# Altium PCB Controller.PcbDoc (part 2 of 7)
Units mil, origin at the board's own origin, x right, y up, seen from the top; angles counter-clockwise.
Board outline 9000 x 8000 mil, 6 copper layers (Top Layer, Layer 1, Layer 2, Layer 3, Layer 4, Bottom Layer), stack 61.699 mil thick; 761 components, 454 nets, 2369 pads, 1133 vias.
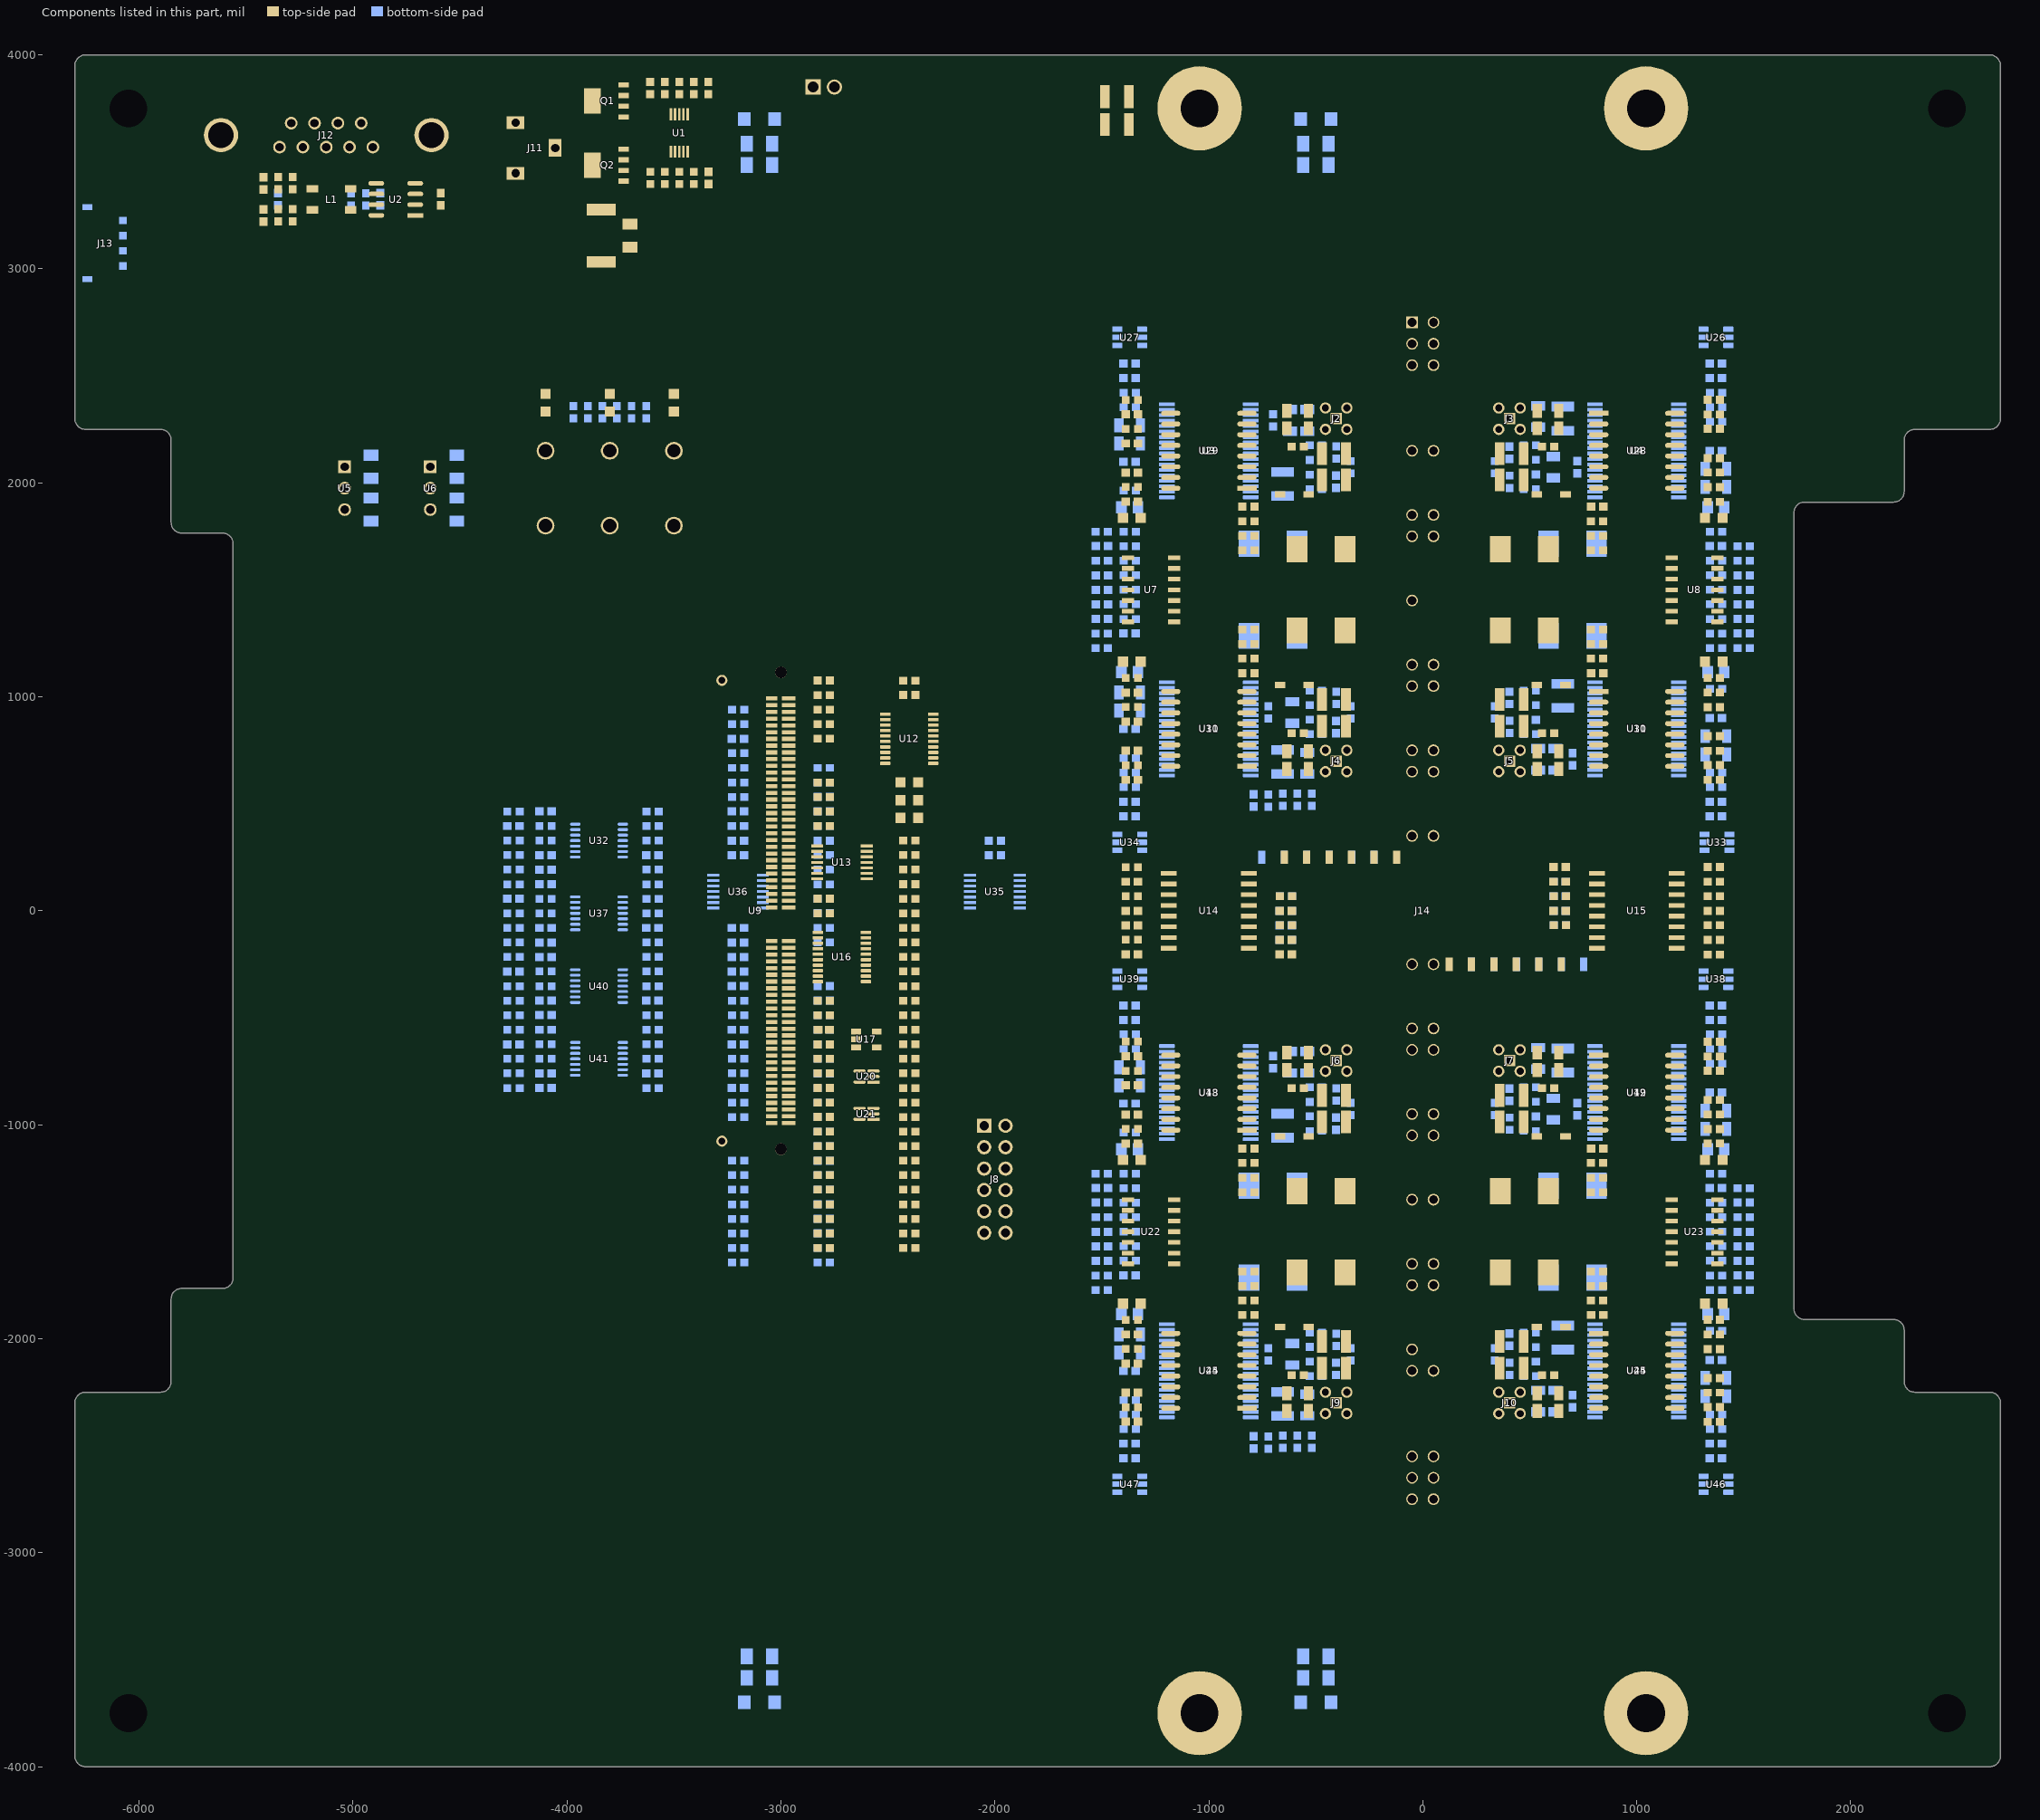
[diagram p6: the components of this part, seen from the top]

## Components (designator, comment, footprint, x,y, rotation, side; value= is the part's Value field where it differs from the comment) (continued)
R219 "RT0603BRD0716K2L" FP-MCR03-IPC_B -500,893 r180 bottom value=16.2kΩ
R220 "RT0603FRE0749K9L" FP-MCR03-IPC_B 405,859 r270 bottom value=49.9kΩ
R222 "CRCW060320K0FKTA" FP-MCR03-IPC_B -3200,872 r0 bottom value=20kΩ
R223 "RT0603DRE0730KL" FP-MCR03-IPC_B 500,825 r0 bottom value=30kΩ
R224 "RT0603BRD07107KL" FP-MCR03-IPC_B -500,825 r0 bottom value=107kΩ
R226 "RC1210JR-07330RL" RESC3125X70X40NL20T20 -655,695 r270 bottom value=330Ω
R227 "CRCW060320K0FKTA" FP-MCR03-IPC_B -3200,736 r0 bottom value=20kΩ
R228 "CRCW06030000Z0EB" FP-MCR03-IPC_B -1370,714 r180 bottom value=0Ω
R229 "RC0603FR-13330RL" FP-MCR03-IPC_B -2800,668 r180 bottom value=330Ω
R230 "CRCW060320K0FKTA" FP-MCR03-IPC_B -3200,668 r180 bottom value=20kΩ
R231 "ERJ3EKF1002V" FP-MCR03-IPC_B 1370,646 r0 bottom value=10kΩ
R232 "ERJ3EKF1002V" FP-MCR03-IPC_B -1370,646 r0 bottom value=10kΩ
R233 "RC0603FR-13330RL" FP-MCR03-IPC_B -2800,600 r180 bottom value=330Ω
R234 "CRCW060320K0FKTA" FP-MCR03-IPC_B -3200,600 r180 bottom value=20kΩ
R235 "RC0603JR-07120RL" FP-MCR03-IPC_B 1370,578 r0 bottom value=120Ω
R236 "RC0603JR-07120RL" FP-MCR03-IPC_B -1370,578 r0 bottom value=120Ω
R237 "CRCW06030000Z0EB" FP-MCR03-IPC_B -518,518 r270 bottom value=0Ω
R238 "RC0603FR-075K1L" FP-MCR03-IPC_B -586,518 r90 bottom value=5.1kΩ
R239 "ERJ-PB3B1801V" FP-MCR03-IPC_B -654,518 r270 bottom value=1.8kΩ
R240 "ERJ-PB3B1801V" FP-MCR03-IPC_B -722,515 r270 bottom value=1.8kΩ
R241 "CRCW060320K0FKTA" FP-MCR03-IPC_B -3200,532 r0 bottom value=20kΩ
R242 "CRCW060320K0FKTA" FP-MCR03-IPC_B -3600,464 r0 bottom value=20kΩ
R243 "CRCW060320K0FKTA" FP-MCR03-IPC_B -4250,464 r0 bottom value=20kΩ
R244 "RC0603FR-0727KL" FP-MCR03-IPC_B -3600,396 r0 bottom value=27kΩ
R245 "RC0603JR-101KL" FP-MCR03-IPC_B -4100,396 r0 bottom value=1kΩ
R246 "RC0603FR-0727KL" FP-MCR03-IPC_B -3600,328 r180 bottom value=27kΩ
R247 "RC0603JR-101KL" FP-MCR03-IPC_B -4100,328 r0 bottom value=1kΩ
R248 "RT0603BRD072K7L" FP-MCR03-IPC_B -4250,328 r0 bottom value=2.7kΩ
R249 "RC0603JR-07120RL" FP-MCR03-IPC_B -2800,260 r0 bottom value=120Ω
R250 "RC0603JR-07120RL" FP-MCR03-IPC_B -4250,260 r0 bottom value=120Ω
R251 "RNCF1206BKE1M00" RESC3116X65X40LL10T20 -280,250 r0 bottom value=1MΩ
R252 "RNCF1206BKE1M00" RESC3116X65X40LL10T20 -490,250 r0 bottom value=1MΩ
R253 "RNCF1206BKE1M00" RESC3116X65X40LL10T20 -700,250 r0 bottom value=1MΩ
R254 "RC0603JR-07120RL" FP-MCR03-IPC_B -2800,192 r0 bottom value=120Ω
R255 "ERJ3EKF1002V" FP-MCR03-IPC_B -3600,192 r180 bottom value=10kΩ
R256 "RT0603BRD072K7L" FP-MCR03-IPC_B -4250,192 r0 bottom value=2.7kΩ
R257 "RC0603JR-07120RL" FP-MCR03-IPC_B -2800,124 r0 bottom value=120Ω
R258 "CRCW060320K0FKTA" FP-MCR03-IPC_B -3600,124 r0 bottom value=20kΩ
R259 "CRCW060320K0FKTA" FP-MCR03-IPC_B -4250,124 r0 bottom value=20kΩ
R260 "ERA-3AEB5621V" FP-MCR03-IPC_B -640,68 r180 bottom value=5.62kΩ
R261 "RC0603JR-07120RL" FP-MCR03-IPC_B -2800,56 r0 bottom value=120Ω
R262 "RC0603FR-0727KL" FP-MCR03-IPC_B -3600,56 r0 bottom value=27kΩ
R263 "RC0603JR-101KL" FP-MCR03-IPC_B -4100,56 r0 bottom value=1kΩ
R264 "RC0603FR-0727KL" FP-MCR03-IPC_B -3600,-12 r180 bottom value=27kΩ
R265 "RC0603JR-101KL" FP-MCR03-IPC_B -4100,-12 r0 bottom value=1kΩ
R266 "RT0603BRD072K7L" FP-MCR03-IPC_B -4250,-12 r0 bottom value=2.7kΩ
R267 "ERA-3AEB5621V" FP-MCR03-IPC_B 640,-68 r0 bottom value=5.62kΩ
R268 "RC0603JR-07120RL" FP-MCR03-IPC_B -4250,-80 r0 bottom value=120Ω
R269 "ERJ3EKF1002V" FP-MCR03-IPC_B -2800,-148 r0 bottom value=10kΩ
R270 "ERJ3EKF1002V" FP-MCR03-IPC_B -3600,-148 r180 bottom value=10kΩ
R271 "RT0603BRD072K7L" FP-MCR03-IPC_B -4250,-148 r0 bottom value=2.7kΩ
R272 "CRCW060320K0FKTA" FP-MCR03-IPC_B -3600,-216 r0 bottom value=20kΩ
R273 "CRCW060320K0FKTA" FP-MCR03-IPC_B -4250,-216 r0 bottom value=20kΩ
R274 "RNCF1206BKE1M00" RESC3116X65X40LL10T20 700,-250 r180 bottom value=1MΩ
R275 "RNCF1206BKE1M00" RESC3116X65X40LL10T20 490,-250 r180 bottom value=1MΩ
R276 "RNCF1206BKE1M00" RESC3116X65X40LL10T20 280,-250 r180 bottom value=1MΩ
R277 "RC0603FR-0727KL" FP-MCR03-IPC_B -3600,-284 r0 bottom value=27kΩ
R278 "RC0603JR-101KL" FP-MCR03-IPC_B -4100,-284 r0 bottom value=1kΩ
R279 "RC0603FR-0727KL" FP-MCR03-IPC_B -3600,-352 r180 bottom value=27kΩ
R280 "RC0603JR-101KL" FP-MCR03-IPC_B -4100,-352 r0 bottom value=1kΩ
R281 "RT0603BRD072K7L" FP-MCR03-IPC_B -4250,-352 r0 bottom value=2.7kΩ
R282 "ERJ-3EKF49R9V" FP-MCR03-IPC_B -3200,-420 r0 bottom value=49.9Ω
R283 "RC0603JR-07120RL" FP-MCR03-IPC_B -4250,-420 r0 bottom value=120Ω
R284 "RC0603FR-075K49L" FP-MCR03-IPC_B -2800,-488 r0 bottom value=5.49kΩ
R285 "ERJ-3EKF49R9V" FP-MCR03-IPC_B -3200,-488 r0 bottom value=49.9Ω
R286 "ERJ3EKF1002V" FP-MCR03-IPC_B -3600,-488 r180 bottom value=10kΩ
R287 "RT0603BRD072K7L" FP-MCR03-IPC_B -4250,-488 r0 bottom value=2.7kΩ
R288 "RC0603FR-13330RL" FP-MCR03-IPC_B -2800,-556 r0 bottom value=330Ω
R289 "CRCW060320K0FKTA" FP-MCR03-IPC_B -3600,-556 r0 bottom value=20kΩ
R290 "CRCW060320K0FKTA" FP-MCR03-IPC_B -4250,-556 r0 bottom value=20kΩ
R291 "RC0603JR-07120RL" FP-MCR03-IPC_B 1370,-578 r180 bottom value=120Ω
R292 "RC0603JR-07120RL" FP-MCR03-IPC_B -1370,-578 r180 bottom value=120Ω
R293 "RC0603FR-0727KL" FP-MCR03-IPC_B -3600,-624 r0 bottom value=27kΩ
R294 "RC0603JR-101KL" FP-MCR03-IPC_B -4100,-624 r0 bottom value=1kΩ
R295 "ERJ3EKF1002V" FP-MCR03-IPC_B 1370,-646 r180 bottom value=10kΩ
R296 "RC1210JR-07330RL" RESC3125X70X40NL20T20 655,-700 r90 bottom value=330Ω
R297 "ERJ3EKF1002V" FP-MCR03-IPC_B -1370,-646 r180 bottom value=10kΩ
R298 "RT0603DRD0716K5L" FP-MCR03-IPC_B -2800,-692 r180 bottom value=16.5kΩ
R299 "ERJ-3EKF49R9V" FP-MCR03-IPC_B -3200,-692 r0 bottom value=49.9Ω
R300 "RC0603FR-0727KL" FP-MCR03-IPC_B -3600,-692 r180 bottom value=27kΩ
R301 "RC0603JR-101KL" FP-MCR03-IPC_B -4100,-692 r0 bottom value=1kΩ
R302 "RT0603BRD072K7L" FP-MCR03-IPC_B -4250,-692 r0 bottom value=2.7kΩ
R303 "CRCW06030000Z0EB" FP-MCR03-IPC_B 1370,-714 r0 bottom value=0Ω
R304 "ERJ-3EKF49R9V" FP-MCR03-IPC_B -3200,-760 r0 bottom value=49.9Ω
R305 "RC0603JR-07120RL" FP-MCR03-IPC_B -4250,-760 r0 bottom value=120Ω
R306 "RT0603BRD07107KL" FP-MCR03-IPC_B 500,-825 r180 bottom value=107kΩ
R307 "RT0603DRE0730KL" FP-MCR03-IPC_B -500,-825 r180 bottom value=30kΩ
R308 "RT0603DRD0716K5L" FP-MCR03-IPC_B -2800,-828 r0 bottom value=16.5kΩ
R309 "ERJ3EKF1002V" FP-MCR03-IPC_B -3600,-828 r180 bottom value=10kΩ
R310 "RT0603BRD072K7L" FP-MCR03-IPC_B -4250,-828 r0 bottom value=2.7kΩ
R311 "RT0603FRE0749K9L" FP-MCR03-IPC_B -405,-859 r90 bottom value=49.9kΩ
R312 "RT0603BRD0716K2L" FP-MCR03-IPC_B 500,-893 r0 bottom value=16.2kΩ
R313 "ERJ3EKF1002V" FP-MCR03-IPC_B -2800,-896 r0 bottom value=10kΩ
R314 "ERJ3EKF1002V" FP-MCR03-IPC_B -3200,-896 r180 bottom value=10kΩ
R315 "ERJ3EKF1002V" FP-MCR03-IPC_B 337,-927 r270 bottom value=10kΩ
R316 "ERJ3EKF1002V" FP-MCR03-IPC_B -337,-927 r270 bottom value=10kΩ
R317 "RC1210JR-07330RL" RESC3125X70X40NL20T20 -655,-1005 r270 bottom value=330Ω
R318 "RT0603BRD0716K2L" FP-MCR03-IPC_B -500,-961 r180 bottom value=16.2kΩ
R319 "ERJ3EKF1002V" FP-MCR03-IPC_B -3200,-964 r180 bottom value=10kΩ
R320 "RT0603FRE0749K9L" FP-MCR03-IPC_B 405,-995 r270 bottom value=49.9kΩ
R321 "RT0603DRE0730KL" FP-MCR03-IPC_B 500,-1029 r0 bottom value=30kΩ
R322 "RT0603BRD07107KL" FP-MCR03-IPC_B -500,-1029 r0 bottom value=107kΩ
R323 "CRCW06030000Z0EB" FP-MCR03-IPC_B -1370,-1037 r180 bottom value=0Ω
R324 "RC0805FR-07499RL" FP-MCR10-IPC_A 1370,-1115 r0 bottom value=499Ω
R325 "RC0805FR-07499RL" FP-MCR10-IPC_A -1370,-1115 r180 bottom value=499Ω
R326 "ERJ3EKF1002V" FP-MCR03-IPC_B -3200,-1168 r0 bottom value=10kΩ
R327 "ERJ3EKF1002V" FP-MCR03-IPC_B 1370,-1228 r180 bottom value=10kΩ
R328 "ERJ3EKF1002V" FP-MCR03-IPC_B -1370,-1228 r0 bottom value=10kΩ
R329 "ERJ3EKF1002V" FP-MCR03-IPC_B -1500,-1228 r180 bottom value=10kΩ
R330 "ERJ3EKF1002V" FP-MCR03-IPC_B -2800,-1236 r0 bottom value=10kΩ
R331 "ERJ3EKF1002V" FP-MCR03-IPC_B -3200,-1236 r0 bottom value=10kΩ
R332 "RC0603JR-07120RL" FP-MCR03-IPC_B 1500,-1296 r0 bottom value=120Ω
R333 "RC0603JR-07120RL" FP-MCR03-IPC_B -1370,-1296 r0 bottom value=120Ω
R334 "ERJ3EKF1002V" FP-MCR03-IPC_B -2800,-1304 r180 bottom value=10kΩ
R335 "ERJ3EKF1002V" FP-MCR03-IPC_B -3200,-1304 r180 bottom value=10kΩ
R336 "ERJ3EKF1002V" FP-MCR03-IPC_B 1370,-1364 r0 bottom value=10kΩ
R337 "RC0603JR-07120RL" FP-MCR03-IPC_B -1370,-1364 r0 bottom value=120Ω
R338 "ERJ3EKF1002V" FP-MCR03-IPC_B -3200,-1372 r180 bottom value=10kΩ
R339 "RC0603JR-07120RL" FP-MCR03-IPC_B 1370,-1432 r180 bottom value=120Ω
R340 "RC0603JR-07120RL" FP-MCR03-IPC_B -1370,-1432 r0 bottom value=120Ω
R341 "ERJ3EKF1002V" FP-MCR03-IPC_B -3200,-1440 r0 bottom value=10kΩ
R342 "RC0603JR-07120RL" FP-MCR03-IPC_B 1370,-1500 r180 bottom value=120Ω
R343 "RC0603JR-07120RL" FP-MCR03-IPC_B -1370,-1500 r0 bottom value=120Ω
R344 "ERJ3EKF1002V" FP-MCR03-IPC_B -3200,-1508 r0 bottom value=10kΩ
R345 "RC0603JR-07120RL" FP-MCR03-IPC_B 1370,-1568 r180 bottom value=120Ω
R346 "RC0603JR-07120RL" FP-MCR03-IPC_B -1370,-1568 r0 bottom value=120Ω
R347 "ERJ3EKF1002V" FP-MCR03-IPC_B -2800,-1576 r0 bottom value=10kΩ
R348 "ERJ3EKF1002V" FP-MCR03-IPC_B -3200,-1576 r180 bottom value=10kΩ
R349 "RC0603JR-07120RL" FP-MCR03-IPC_B 1370,-1636 r180 bottom value=120Ω
R350 "ERJ3EKF1002V" FP-MCR03-IPC_B -1370,-1636 r180 bottom value=10kΩ
R351 "ERJ3EKF1002V" FP-MCR03-IPC_B -2800,-1644 r0 bottom value=10kΩ
R352 "ERJ3EKF1002V" FP-MCR03-IPC_B -3200,-1644 r180 bottom value=10kΩ
R353 "RC0603JR-07120RL" FP-MCR03-IPC_B 1370,-1704 r180 bottom value=120Ω
R354 "RC0603JR-07120RL" FP-MCR03-IPC_B -1500,-1704 r180 bottom value=120Ω
R355 "ERJ3EKF1002V" FP-MCR03-IPC_B 1500,-1772 r0 bottom value=10kΩ
R356 "ERJ3EKF1002V" FP-MCR03-IPC_B 1370,-1772 r180 bottom value=10kΩ
R357 "ERJ3EKF1002V" FP-MCR03-IPC_B -1500,-1772 r0 bottom value=10kΩ
R358 "RC0805FR-07499RL" FP-MCR10-IPC_A 1370,-1885 r0 bottom value=499Ω
R359 "RC0805FR-07499RL" FP-MCR10-IPC_A -1370,-1885 r180 bottom value=499Ω
R360 "RC1210JR-07330RL" RESC3125X70X40NL20T20 655,-1995 r90 bottom value=330Ω
R361 "CRCW06030000Z0EB" FP-MCR03-IPC_B 1370,-1963 r0 bottom value=0Ω
R362 "RT0603BRD07107KL" FP-MCR03-IPC_B 500,-1971 r180 bottom value=107kΩ
R363 "RT0603DRE0730KL" FP-MCR03-IPC_B -500,-1971 r180 bottom value=30kΩ
R364 "RT0603FRE0749K9L" FP-MCR03-IPC_B -405,-2005 r90 bottom value=49.9kΩ
R365 "RT0603BRD0716K2L" FP-MCR03-IPC_B 500,-2039 r0 bottom value=16.2kΩ
R366 "ERJ3EKF1002V" FP-MCR03-IPC_B 337,-2073 r90 bottom value=10kΩ
R367 "ERJ3EKF1002V" FP-MCR03-IPC_B -337,-2073 r90 bottom value=10kΩ
R368 "RT0603BRD0716K2L" FP-MCR03-IPC_B -500,-2107 r180 bottom value=16.2kΩ
R369 "RT0603FRE0749K9L" FP-MCR03-IPC_B 405,-2141 r270 bottom value=49.9kΩ
R370 "RT0603DRE0730KL" FP-MCR03-IPC_B 500,-2175 r0 bottom value=30kΩ
R371 "RT0603BRD07107KL" FP-MCR03-IPC_B -500,-2175 r0 bottom value=107kΩ
R372 "RC1210JR-07330RL" RESC3125X70X40NL20T20 -655,-2305 r270 bottom value=330Ω
R373 "CRCW06030000Z0EB" FP-MCR03-IPC_B -1370,-2286 r180 bottom value=0Ω
R374 "ERJ3EKF1002V" FP-MCR03-IPC_B 1370,-2354 r180 bottom value=10kΩ
R375 "ERJ3EKF1002V" FP-MCR03-IPC_B -1370,-2354 r0 bottom value=10kΩ
R376 "RC0603JR-07120RL" FP-MCR03-IPC_B 1370,-2422 r0 bottom value=120Ω
R377 "RC0603JR-07120RL" FP-MCR03-IPC_B -1370,-2422 r0 bottom value=120Ω
R378 "CRCW06030000Z0EB" FP-MCR03-IPC_B -518,-2482 r270 bottom value=0Ω
R379 "RC0603FR-075K1L" FP-MCR03-IPC_B -586,-2482 r90 bottom value=5.1kΩ
R380 "ERJ-PB3B1801V" FP-MCR03-IPC_B -654,-2482 r270 bottom value=1.8kΩ
R381 "ERJ-PB3B1801V" FP-MCR03-IPC_B -722,-2485 r270 bottom value=1.8kΩ
R382 "RC1206FR-07249RL" FP-MCR18-IPC_A -500,-3485 r180 bottom value=249Ω
R383 "RC1206FR-07249RL" FP-MCR18-IPC_A -3100,-3485 r0 bottom value=249Ω
R384 "RC1206FR-07249RL" FP-MCR18-IPC_A -500,-3585 r0 bottom value=249Ω
R385 "RC1206FR-07249RL" FP-MCR18-IPC_A -3100,-3585 r180 bottom value=249Ω
TP1 "5010" KSTN-5010_V -4100,2150 r0 top value=RED
TP2 "5010" KSTN-5010_V -3800,2150 r0 top value=RED
TP3 "5010" KSTN-5010_V -3500,2150 r0 top value=RED
TP4 "5011" KSTN-5011_V -4100,1800 r0 top value=BLACK
TP5 "5011" KSTN-5011_V -3800,1800 r0 top value=BLACK
TP6 "5011" KSTN-5011_V -3500,1800 r0 top value=BLACK
U1 "LTC4368IMS-2#PBF" SOP50P490X110-10N -3475,3635 r270 top value=N/A
U2 "TCAN1044VDRQ1" FP-D0008A-IPC_C -4800,3325 r180 top value=N/A
U3 "UCC21710QDWRQ1" FP-DW0016B-IPC_B -1000,2150 r180 top locked value=N/A
U4 "UCC21710QDWRQ1" FP-DW0016B-IPC_B 1000,2150 r0 top locked value=N/A
U5 "R-78E3.3-1.0" CONV_R-78E3.3-1.0 -4950,1975 r270 top value=N/A
U6 "R-78E5.0-1.0" CONV_R-78E5.0-1.0 -4550,1975 r270 top value=N/A
U7 "SN74HCS21DR" SOIC_S21DR_TEX -1270,1500 r180 top value=N/A
U8 "SN74HCS21DR" SOIC_S21DR_TEX 1270,1500 r0 top value=N/A
U9 "TMDSCNCD280039C" TMDSCNCD280039C_HORZ -3000,0 r270 top locked value=N/A
U10 "UCC21710QDWRQ1" FP-DW0016B-IPC_B -1000,850 r180 top locked value=N/A
U11 "UCC21710QDWRQ1" FP-DW0016B-IPC_B 1000,850 r0 top locked value=N/A
U12 "SN74LV541ATPWR" PW0020A_L -2400,804 r0 top value=N/A
U13 "TXU0104QPWRQ1" SOIC_QPWRQ1_TEX -2715,226 r180 top value=N/A
U14 "AMC3330QDWERQ1" SOIC16_DWE_TEX -1000,0 r180 top value=N/A
U15 "AMC3330QDWERQ1" SOIC16_DWE_TEX 1000,0 r0 top value=N/A
U16 "SN74LV541ATPWR" PW0020A_L -2715,-216 r0 top locked value=N/A
U17 "AD8615AUJZ-REEL7" ADI-UJ-5_M -2600,-601 r0 top value=N/A
U18 "UCC21710QDWRQ1" FP-DW0016B-IPC_B -1000,-850 r180 top locked value=N/A
U19 "UCC21710QDWRQ1" FP-DW0016B-IPC_B 1000,-850 r0 top locked value=N/A
U20 "TLV6001QDCKRQ1" FP-DCK0005A-IPC_B -2600,-775 r180 top value=N/A
U21 "TLV6001QDCKRQ1" FP-DCK0005A-IPC_B -2600,-949 r180 top value=N/A
U22 "SN74HCS21DR" SOIC_S21DR_TEX -1270,-1500 r180 top value=N/A
U23 "SN74HCS21DR" SOIC_S21DR_TEX 1270,-1500 r0 top value=N/A
U24 "UCC21710QDWRQ1" FP-DW0016B-IPC_B -1000,-2150 r180 top locked value=N/A
U25 "UCC21710QDWRQ1" FP-DW0016B-IPC_B 1000,-2150 r0 top locked value=N/A
U26 "SN74LVC2G14DBVR" DBV0006A_M 1370,2680 r0 bottom value=N/A
U27 "SN74LVC2G14DBVR" DBV0006A_M -1370,2680 r180 bottom value=N/A
U28 "UCC14141QDWNRQ1" DWN0036-IPC-MFG 1000,2150 r0 bottom value=N/A
U29 "UCC14141QDWNRQ1" DWN0036-IPC-MFG -1000,2150 r180 bottom value=N/A
U30 "UCC14141QDWNRQ1" DWN0036-IPC-MFG 1000,850 r0 bottom locked value=N/A
U31 "UCC14141QDWNRQ1" DWN0036-IPC-MFG -1000,850 r180 bottom locked value=N/A
U32 "AD8618ARUZ-REEL" ADI-RU-14_L -3850,328 r0 bottom value=N/A
U33 "SN74LVC2G14DBVR" DBV0006A_M 1375,320 r0 bottom value=N/A
U34 "SN74LVC2G14DBVR" DBV0006A_M -1370,320 r180 bottom value=N/A
U35 "TXU0104QPWRQ1" SOIC_QPWRQ1_TEX -2000,90 r180 bottom value=N/A
U36 "TXU0104QPWRQ1" SOIC_QPWRQ1_TEX -3200,90 r180 bottom value=N/A
U37 "AD8618ARUZ-REEL" ADI-RU-14_L -3850,-12 r0 bottom value=N/A
U38 "SN74LVC2G14DBVR" DBV0006A_M 1370,-320 r0 bottom value=N/A
U39 "SN74LVC2G14DBVR" DBV0006A_M -1370,-320 r180 bottom value=N/A
U40 "AD8618ARUZ-REEL" ADI-RU-14_L -3850,-352 r0 bottom value=N/A
U41 "AD8618ARUZ-REEL" ADI-RU-14_L -3850,-692 r0 bottom value=N/A
U42 "UCC14141QDWNRQ1" DWN0036-IPC-MFG 1000,-850 r0 bottom value=N/A
U43 "UCC14141QDWNRQ1" DWN0036-IPC-MFG -1000,-850 r180 bottom value=N/A
U44 "UCC14141QDWNRQ1" DWN0036-IPC-MFG 1000,-2150 r0 bottom locked value=N/A
U45 "UCC14141QDWNRQ1" DWN0036-IPC-MFG -1000,-2150 r180 bottom locked value=N/A
U46 "SN74LVC2G14DBVR" DBV0006A_M 1370,-2680 r0 bottom value=N/A
U47 "SN74LVC2G14DBVR" DBV0006A_M -1370,-2680 r180 bottom value=N/A

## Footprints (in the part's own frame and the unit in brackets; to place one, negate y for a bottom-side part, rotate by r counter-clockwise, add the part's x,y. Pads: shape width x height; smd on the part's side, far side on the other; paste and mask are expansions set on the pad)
2082940040 [mm]
  rect 0.9x0.95 smd: 1(-2.7,0) 2(-0.9,0) 3(0.9,0) 4(2.7,0)
  rect 0.7x1.2 smd: MH1(-4.265,-4.225) MH2(4.265,-4.225)
  silkscreen extent -4.55,-5.43 4.55,-0.18, body extent -4.55,-5.46 4.55,0.25, height 1.6
ADI-RU-14_L [mm] "SOP, 14-Leads, Body 5x4.4mm, Pitch 0.65mm, IPC High Density"
  oval 1.25x0.35 smd: 1(-2.825,1.95) 2(-2.825,1.3) 3(-2.825,0.65) 4(-2.825,0) 5(-2.825,-0.65) 6(-2.825,-1.3) 7(-2.825,-1.95) 8(2.825,-1.95) 9(2.825,-1.3) 10(2.825,-0.65) 11(2.825,0) 12(2.825,0.65) 13(2.825,1.3) 14(2.825,1.95)
  silkscreen extent -2.95,-2.55 1.8,2.8, body extent -2.25,-2.55 2.25,2.55, height 1.2
ADI-UJ-5_M [mm] "SOT23, 5-Leads, Body 2.9x1.6mm, Pitch 0.95mm, IPC Low Density"
  rect 1.15x0.7 smd: 1(-1.225,0.95) 2(-1.225,0) 3(-1.225,-0.95) 4(1.225,-0.95) 5(1.225,0.95)
  silkscreen extent -1.35,-1.45 0.25,1.97, body extent -0.8,-1.45 0.8,1.45, height 1
CONV_R-78E3.3-1.0 [mm]
  rect 1.508x1.508 hole 1: 1(-2.54,-2.25)
  round 1.508 hole 1: 2(0,-2.25) 3(2.54,-2.25)
  silkscreen extent -6.5,-4.25 5.75,4.25, body extent -5.8,-4.25 5.8,4.25, height 9.9
CONV_R-78E5.0-1.0 [mm]
  rect 1.508x1.508 hole 1: 1(-2.54,-2.25)
  round 1.508 hole 1: 2(0,-2.25) 3(2.54,-2.25)
  silkscreen extent -6.5,-4.25 5.75,4.25, body extent -5.8,-4.25 5.8,4.25, height 9.9
CUI-PJ-102B_V [mm] "THD, 3-Leads, Body 14.4x9mm, Height 11mm"
  rect 1.5x2.1 hole 1 slot 1.6 at 90 deg: 1(-3,0) 2(3,0)
  rect 2.1x1.5 hole 1 slot 1.6 at 0 deg: 3(0,4.7)
  silkscreen extent -4.42,-4.5 10.7,4.9, body extent -3.7,-4.5 10.7,4.9, height 11
DBV0006A_M [mm] "SOT23, 6-Leads, Body 3.05x1.75mm, Pitch 0.95mm, IPC Low Density"
  rrect15% 1.2x0.65 smd: 1(-1.475,0.95) 2(-1.475,0) 3(-1.475,-0.95) 4(1.475,-0.95) 5(1.475,0) 6(1.475,0.95)
  silkscreen extent -1.6,-1.55 0.5,1.95, body extent -1.42,-1.46 1.42,1.46, height 1.11
DIOM6959X25N [mm] "Molded Diode, 2-Leads, Body 6.86x5.91mm, IPC Medium Density"
  rect 2.45x3.1 smd: 1(-2.85,0) 2(2.85,0)
  silkscreen extent -4.38,-3.15 3.6,3.15, body extent -3.55,-3.11 3.56,3.11, height 2.5
DWN0036-IPC-MFG [mm]
  rrect22% 1.85x0.45 smd paste+0 mask+0: 1(4.975,-5.525) 2(4.975,-4.875) 3(4.975,-4.225) 4(4.975,-3.575) 5(4.975,-2.925) 6(4.975,-2.275) 7(4.975,-1.625) 8(4.975,-0.975) 9(4.975,-0.325) 10(4.975,0.325) 11(4.975,0.975) 12(4.975,1.625) 13(4.975,2.275) 14(4.975,2.925) 15(4.975,3.575) 16(4.975,4.225) 17(4.975,4.875) 18(4.975,5.525) 19(-4.975,5.525) 20(-4.975,4.875) 21(-4.975,4.225) 22(-4.975,3.575) 23(-4.975,2.925) 24(-4.975,2.275) 25(-4.975,1.625) 26(-4.975,0.975) 27(-4.975,0.325) 28(-4.975,-0.325) 29(-4.975,-0.975) 30(-4.975,-1.625) 31(-4.975,-2.275) 32(-4.975,-2.925) 33(-4.975,-3.575) 34(-4.975,-4.225) 35(-4.975,-4.875) 36(-4.975,-5.525)
  silkscreen extent -3.8,-6.47 6.32,6.47, body extent -5.15,-6.42 5.15,6.42, height 3.55
FP-73415-1471-MFG [mm]
  rect 1.34x1.34 hole 0.84 paste-2539.97 mask+0: 1(0.01,0)
  round 1.34 hole 0.84 paste-2539.97 mask+0: 2(-1.27,1.27) 3(1.27,1.27) 4(-1.27,-1.27) 5(1.27,-1.27)
  silkscreen extent -2.54,-1.82 1.82,1.82, body extent -2.04,-2.04 2.04,2.04, height 0.25
FP-61301221121-MFG [mm]
  rect 1.7x1.7 hole 1.1 paste-2539.97 mask+0: 1(-6.35,-1.27)
  round 1.7 hole 1.1 paste-2539.97 mask+0: 2(-6.35,1.27) 3(-3.81,-1.27) 4(-3.81,1.27) 5(-1.27,-1.27) 6(-1.27,1.27) 7(1.27,-1.27) 8(1.27,1.27) 9(3.81,-1.27) 10(3.81,1.27) 11(6.35,-1.27) 12(6.35,1.27)
  silkscreen extent -8.38,-2.62 7.77,2.62, body extent -7.87,-2.72 7.87,2.72, height 0.25
FP-APTR3216SECK-MFG [mm]
  rect 1.5x1.6 smd paste+0 mask+0: 1(-1.8,0) 2(1.8,0)
  silkscreen extent -3.3,-1.4 1.9,1.4, body extent -1.6,-0.8 1.6,0.8, height 1.1
FP-C0603C-CF-IPC_B [mil]
  rect 39.63x37.73 smd paste+0 mask+0: 1(-28.58,0) 2(28.58,0)
  silkscreen extent -48,-35 48,35, body extent -58,-29 58,29, height 10
FP-CL31-IPC_B [mil]
  rect 51.4x69.22 smd paste+0 mask+0: 1(-54.19,0) 2(54.19,0)
  silkscreen extent -17,-35 17,35, body extent -90,-44 90,44, height 10
FP-CL31-IPC_C [mil]
  rect 43.52x65.28 smd paste+0 mask+0: 1(-50.25,0) 2(50.25,0)
  silkscreen extent -17,-34 17,34, body extent -76,-38 76,38, height 10
FP-D0008A-IPC_C [mil]
  rect 73.59x21.34 smd paste+0 mask+0: 1(-91.09,75)
  rrect100% 73.59x21.34 smd paste+0 mask+0: 2(-91.09,25) 3(-91.09,-25) 4(-91.09,-75) 5(91.09,-75) 6(91.09,-25) 7(91.09,25) 8(91.09,75)
  silkscreen extent -154,-97 35,97, body extent -132,-100 132,100, height 10
FP-DCK0005A-IPC_B [mm]
  rect 1.464x0.376 smd paste+0 mask+0: 1(-0.82,0.65)
  rrect100% 1.464x0.376 smd paste+0 mask+0: 2(-0.82,0) 3(-0.82,-0.65) 4(0.82,-0.65) 5(0.82,0.65)
  silkscreen extent -2.23,-1.25 1.05,1.25, body extent -1.8,-1.25 1.8,1.25, height 0.25
FP-DLW43-0_2-t2_6-e0_6-MFG [mm]
  rect 1.35x0.9 smd paste+0 mask+0: 1(-2.275,-1.25) 2(2.275,-1.25) 3(2.275,1.25) 4(-2.275,1.25)
  silkscreen extent -3.65,-1.7 2.35,1.7, body extent -3.05,-1.8 3.05,1.8, height 2.8
FP-DW0016B-IPC_B [mil] "SOIC-16W"
  rect 90.66x22.92 smd paste+0 mask+0: 1(-177.78,175)
  rrect100% 90.66x22.92 smd paste+0 mask+0: 2(-177.78,125) 3(-177.78,75) 4(-177.78,25) 5(-177.78,-25) 6(-177.78,-75) 7(-177.78,-125) 8(-177.78,-175) 9(177.78,-175) 10(177.78,-125) 11(177.78,-75) 12(177.78,-25) 13(177.78,25) 14(177.78,75) 15(177.78,125) 16(177.78,175)
  silkscreen extent -250,-203 113,203, body extent -203,-197 203,197, height 91
FP-LTST-C171GKT-MFG [mm]
  rect 1.2x1.2 smd paste+0 mask+0: 1(-1.05,0) 2(1.05,0)
  silkscreen extent -1.05,-1.05 1.05,1.05, body extent -1.75,-0.77 1.75,0.77, height 0.25
FP-LTST-C171GKT-MFG-RED [mm]
  rect 1.2x1.2 smd paste+0 mask+0: 1(-1.05,0) 2(1.05,0)
  silkscreen extent -1.05,-1.05 1.05,1.05, body extent -1,-0.63 1,0.63, height 0.8
FP-LTST-C171GKT-MFG-YELLOW [mm]
  rect 1.2x1.2 smd paste+0 mask+0: 1(-1.05,0) 2(1.05,0)
  silkscreen extent -1.05,-1.05 1.05,1.05, body extent -1,-0.63 1,0.63, height 0.8
FP-MCR03-IPC_B [mil]
  rect 37.72x35.91 smd paste+0 mask+0: 1(-28.62,0) 2(28.62,0)
  silkscreen extent -47,-34 47,34, body extent -57,-28 57,28, height 10
FP-MCR10-IPC_A [mil]
  rect 49.53x57.56 smd paste+0 mask+0: 1(-38.46,0) 2(38.46,0)
  silkscreen extent -63,-45 63,45, body extent -39,-25 39,25, height 26
FP-MCR18-IPC_A [mil]
  rect 57.31x73.16 smd paste+0 mask+0: 1(-59.1,0) 2(59.1,0)
  silkscreen extent -19,-37 19,37, body extent -63,-31 63,31, height 26
FP-NCU18-0_15-IPC_B [mil]
  rect 43.55x37.73 smd paste+0 mask+0: 1(-26.62,0) 2(26.62,0)
  silkscreen extent -48,-35 48,35, body extent -58,-29 58,29, height 10
FP-PowerDI5060-8-MFG [mm]
  rect 0.61x1.27 smd paste+0 mask+0: 1(-1.905,-2.67) 2(-0.635,-2.67) 3(0.635,-2.67) 4(1.905,-2.67)
  rect 3x2 smd paste+0 mask+0: 5(0,1.05)
  Top Layer region: 2.05,-1.215 -2.05,-1.215 -2.05,-1.035 -2.805,-1.035 -2.805,-0.435 -2.05,-0.435 -2.05,1.39 -2.805,1.39 -2.805,1.99 -2.05,1.99 -2.05,2.285 -2.21,2.285 -2.21,3.305 -1.6,3.305 -1.6,2.595 -0.94,2.595 -0.94,3.305 -0.33,3.305 -0.33,2.595 0.33,2.595 0.33,3.305 0.94,3.305 0.94,2.595 1.6,2.595 1.6,3.305 2.21,3.305 2.21,2.285 2.05,2.285 2.05,1.99 2.805,1.99 2.805,1.39 2.05,1.39 2.05,-0.435 2.805,-0.435 2.805,-1.035 2.05,-1.035
  silkscreen extent -3.2,-2.74 2.55,-1.59, body extent -2.91,-3.4 2.91,3.4, height 0.25
FP-RL2512-IPC_A [mil]
  rect 53.47x136.15 smd paste+0 mask+0: 1(-122.13,0) 2(122.13,0)
  silkscreen extent -84,-68 84,68, body extent -169,-88 169,88, height 10
KSTN-5010_V [mm] "Test Point, Dia 3.17mm"
  round 2.1 hole 1.6: 1(0,0)
  silkscreen extent -1.59,-1.58 1.59,1.58, body extent -1.59,-1.59 1.59,1.59, height 8.13
KSTN-5011_V [mm] "Test Point, Dia 3.17mm"
  round 2.1 hole 1.6: 1(0,0)
  silkscreen extent -1.59,-1.58 1.59,1.58, body extent -1.59,-1.59 1.59,1.59, height 8.13
L717SDE09PA4CH4RC309 [mm] "CONN D-SUB PLUG 9POS R/A SLDR"
  round 1.508 hole 1: 1(-5.54,1.42) 2(-2.77,1.42) 3(0,1.42) 4(2.77,1.42) 5(5.54,1.42) 6(-4.155,-1.42) 7(-1.385,-1.42) 8(1.385,-1.42) 9(4.155,-1.42)
  round 4.066 hole 3.05: 10(-12.495,0) 11(12.495,0)
  silkscreen extent -15.7,-8.5 15.7,3.4, body extent -15.4,-15.6 15.41,3, height 12.55
MH_M4_NP [mm] "M4 non-plated mounting hole"
  round 0 hole 4.5 unplated: 1(0,0)
  body extent -4.5,-4.5 4.49,4.5, height 4.28
MH_M4_P [mm] "M4 plated mounting hole"
  round 10 hole 4.5: 1(0,0)
  body extent -4.44,-4.49 4.55,4.5, height 3.62
PW0020A_L [mm] "SOP, 20-Leads, Body 6.6x4.5mm, Pitch 0.65mm, IPC High Density"
  rrect25% 1.2x0.4 smd: 1(-2.85,2.925) 2(-2.85,2.275) 3(-2.85,1.625) 4(-2.85,0.975) 5(-2.85,0.325) 6(-2.85,-0.325) 7(-2.85,-0.975) 8(-2.85,-1.625) 9(-2.85,-2.275) 10(-2.85,-2.925) 11(2.85,-2.925) 12(2.85,-2.275) 13(2.85,-1.625) 14(2.85,-0.975) 15(2.85,-0.325) 16(2.85,0.325) 17(2.85,0.975) 18(2.85,1.625) 19(2.85,2.275) 20(2.85,2.925)
  silkscreen extent -2.97,-3.3 1.85,3.8, body extent -3.21,-3.25 3.21,3.25, height 1
RESC3116X65X40LL10T20 [mm] "Chip Resistor, 2-Leads, Body 3.10x1.60mm, IPC High Density"
  rect 0.85x1.6 smd: 1(-1.325,0) 2(1.325,0)
  silkscreen extent -0.5,-0.7 0.5,0.7, body extent -1.6,-0.85 1.6,0.85, height 0.65
RESC3125X70X40NL20T20 [mm] "Chip Resistor, 2-Leads, Body 3.10x2.50mm, IPC Medium Density"
  rect 1.15x2.7 smd: 1(-1.425,0) 2(1.425,0)
  silkscreen extent -0.45,-1.25 0.45,1.25, body extent -1.65,-1.35 1.65,1.35, height 0.7
SAMTEC_SSW-126-01-G-D_DUAL_CUSTOM [mm]
  rect 1.39x1.39 / inner round 1.39 / far side rect 1.39x1.39 hole 1.04: 001(69.85,-1.27)
  round 1.39 hole 1.04: 002(69.85,1.27) 003(67.31,-1.27) 004(67.31,1.27) 005(64.77,-1.27) 006(64.77,1.27) 013(54.61,-1.27) 014(54.61,1.27) 019(46.99,-1.27) 020(46.99,1.27) 021(44.45,-1.27) 022(44.45,1.27) 027(36.83,-1.27) 033(29.21,-1.27) 034(29.21,1.27) 035(26.67,-1.27) 036(26.67,1.27) 041(19.05,-1.27) 042(19.05,1.27) 043(16.51,-1.27) 044(16.51,1.27) 049(8.89,-1.27) 050(8.89,1.27) 061(-6.35,-1.27) 062(-6.35,1.27) 067(-13.97,-1.27) 068(-13.97,1.27) 069(-16.51,-1.27) 070(-16.51,1.27) 075(-24.13,-1.27) 076(-24.13,1.27) 077(-26.67,-1.27) 078(-26.67,1.27) 083(-34.29,-1.27) 084(-34.29,1.27) 089(-41.91,-1.27) 090(-41.91,1.27) 091(-44.45,-1.27) 092(-44.45,1.27) 097(-52.07,-1.27) 099(-54.61,-1.27) 100(-54.61,1.27) 107(-64.77,-1.27) 108(-64.77,1.27) 109(-67.31,-1.27) 110(-67.31,1.27) 111(-69.85,-1.27) 112(-69.85,1.27)
  silkscreen extent -71.38,-2.48 72.12,2.48, body extent -71.38,-2.47 71.37,2.48, height 8.53
SOD3716X135N [mm]
  rect 1.25x0.75 smd: 1(-1.7,0) 2(1.7,0)
  silkscreen extent -1.35,-0.77 1.35,0.77, body extent -1.85,-0.86 1.85,0.84, height 1.26
SOIC16_DWE_TEX [mil]
  rect 74x22 smd paste+0 mask+0: 1(-186.5,175) 2(-186.5,125) 3(-186.5,75) 4(-186.5,25) 5(-186.5,-25) 6(-186.5,-75) 7(-186.5,-125) 8(-186.5,-175) 9(186.5,-175) 10(186.5,-125) 11(186.5,-75) 12(186.5,-25) 13(186.5,25) 14(186.5,75) 15(186.5,125) 16(186.5,175)
  silkscreen extent -155,-212 244,212, body extent -209,-206 209,206, height 104
SOIC_QPWRQ1_TEX [mil]
  rect 55.5x14 smd paste+0 mask+0: 1(-116.25,76.77) 2(-116.25,51.18) 3(-116.25,25.59) 4(-116.25,0) 5(-116.25,-25.59) 6(-116.25,-51.18) 7(-116.25,-76.77) 8(116.25,-76.77) 9(116.25,-51.18) 10(116.25,-25.59) 11(116.25,0) 12(116.25,25.59) 13(116.25,51.18) 14(116.25,76.77)
  silkscreen extent -94,-106 164,106, body extent -130,-101 130,101, height 47
SOIC_S21DR_TEX [mil]
  rect 57.5x22 smd paste+0 mask+0: 1(-107.25,150) 2(-107.25,100) 3(-107.25,50) 4(-107.25,0) 5(-107.25,-50) 6(-107.25,-100) 7(-107.25,-150) 8(107.25,-150) 9(107.25,-100) 10(107.25,-50) 11(107.25,0) 12(107.25,50) 13(107.25,100) 14(107.25,150)
  silkscreen extent -84,-177 84,177, body extent -122,-172 122,172, height 69
SOP50P490X110-10N [mm]
  rect 1.425x0.3 smd: 1(-2.212,1) 2(-2.212,0.5) 3(-2.212,0) 4(-2.212,-0.5) 5(-2.212,-1) 6(2.212,-1) 7(2.212,-0.5) 8(2.212,0) 9(2.212,0.5) 10(2.212,1)
  silkscreen extent -2.92,-1.5 1.15,1.5, body extent -2.45,-1.5 2.45,1.5, height 1.1
TECO-640456-2_V [mm] "HDR, 2-Leads, Body 5.715x5.08mm, Pitch 2.54mm"
  rect 1.8x1.8 hole 1.3: 1(1.27,0)
  round 1.8 hole 1.3: 2(-1.27,0)
  silkscreen extent -2.54,-2.54 3.26,3.18, body extent -2.54,-2.67 2.54,3.17, height 10.09
TMDSCNCD280039C_HORZ [mm]
  rect 0.5x1.65 smd: 1(25.2,0.925) 3(24.4,0.925) 5(23.6,0.925) 7(22.8,0.925) 9(22,0.925) 11(21.2,0.925) 13(20.4,0.925) 15(19.6,0.925) 17(18.8,0.925) 19(18,0.925) 21(17.2,0.925) 23(16.4,0.925) 25(15.6,0.925) 27(14.8,0.925) 29(14,0.925) 31(13.2,0.925) 33(12.4,0.925) 35(11.6,0.925) 37(10.8,0.925) 39(10,0.925) 41(9.2,0.925) 43(8.4,0.925) 45(7.6,0.925) 47(6.8,0.925) 49(6,0.925) 51(5.2,0.925) 53(4.4,0.925) 55(3.6,0.925) 57(-0.4,0.925) 59(-1.2,0.925) 61(-2,0.925) 63(-2.8,0.925) 65(-3.6,0.925) 67(-4.4,0.925) 69(-5.2,0.925) 71(-6,0.925) 73(-6.8,0.925) 75(-7.6,0.925) 77(-8.4,0.925) 79(-9.2,0.925) 81(-10,0.925) 83(-10.8,0.925) 85(-11.6,0.925) 87(-12.4,0.925) 89(-13.2,0.925) 91(-14,0.925) 93(-14.8,0.925) 95(-15.6,0.925) 97(-16.4,0.925) 99(-17.2,0.925) 101(-18,0.925) 103(-18.8,0.925) 105(-19.6,0.925) 107(-20.4,0.925) 109(-21.2,0.925) 111(-22,0.925) 113(-22.8,0.925) 115(-23.6,0.925) 117(-24.4,0.925) 119(-25.2,0.925)
  rect 0.5x1.35 smd: 2(25.2,-1.075) 4(24.4,-1.075) 6(23.6,-1.075) 8(22.8,-1.075) 10(22,-1.075) 12(21.2,-1.075) 14(20.4,-1.075) 16(19.6,-1.075) 18(18.8,-1.075) 20(18,-1.075) 22(17.2,-1.075) 24(16.4,-1.075) 26(15.6,-1.075) 28(14.8,-1.075) 30(14,-1.075) 32(13.2,-1.075) 34(12.4,-1.075) 36(11.6,-1.075) 38(10.8,-1.075) 40(10,-1.075) 42(9.2,-1.075) 44(8.4,-1.075) 46(7.6,-1.075) 48(6.8,-1.075) 50(6,-1.075) 52(5.2,-1.075) 54(4.4,-1.075) 56(3.6,-1.075) 58(-0.4,-1.075) 60(-1.2,-1.075) 62(-2,-1.075) 64(-2.8,-1.075) 66(-3.6,-1.075) 68(-4.4,-1.075) 70(-5.2,-1.075) 72(-6,-1.075) 74(-6.8,-1.075) 76(-7.6,-1.075) 78(-8.4,-1.075) 80(-9.2,-1.075) 82(-10,-1.075) 84(-10.8,-1.075) 86(-11.6,-1.075) 88(-12.4,-1.075) 90(-13.2,-1.075) 92(-14,-1.075) 94(-14.8,-1.075) 96(-15.6,-1.075) 98(-16.4,-1.075) 100(-17.2,-1.075) 102(-18,-1.075) 104(-18.8,-1.075) 106(-19.6,-1.075) 108(-20.4,-1.075) 110(-21.2,-1.075) 112(-22,-1.075) 114(-22.8,-1.075) 116(-23.6,-1.075) 118(-24.4,-1.075) 120(-25.2,-1.075)
  round 1.318 hole 0.81: MH1(27.35,-7) MH2(-27.35,-7)
  round 1.4 hole 1.4 unplated: ""(-28.3,0) ""(28.3,0)
  silkscreen extent -30.7,-9 29.9,2.75, body extent -34.14,-58.88 34.41,2.75, height 8.69

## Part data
C1 C10 C13 C14 C15 C16 C17 C19 C20 C21 C22 C24 C25 C27 C28 C29 C30 C31 C34 C59 C62 C63 C65 C66 C68 C70 C71 C72 C73 C74 C76 C77 C78 C79 C80 C83 C91 C92 C116 C117 C118 C119 C120 C121 C122 C123 C124 C125 C126 C127 C151 C152 C153 C154 C159 C160 C163 C176 C179 C183 C185 C197 C198 C224 C228 C229 C230 C232 C233 C234 C235 C236 C237 C238 C239 C240 C241 C242 C243 C244 C245 C246 C267 C268: "CAP CER 56PF 50V C0G/NP0 0603", Capacitance=56pF, Case Code (Imperial)=0603, Case Code (Metric)=1608, Dielectric=C0G, Manufacturer=SAMSUNG, Max Operating Temperature=125°C, Min Operating Temperature=-55°C, Package Quantity=1, Temperature Coefficient=30ppm/°C, TOLERANCE=5%, Voltage=50V
C2 C88: "CAP CER 4700PF 25V 10% X7R 0603", Capacitance=4.7nF, Case Code (Imperial)=0603, Case Code (Metric)=1608, Dielectric=X7R, Dielectric Material=Ceramic, Manufacturer=KEMET, Manufacturer Part Number=C0603C472K3RACTU, Max Operating Temperature=125°C, Min Operating Temperature=-55°C, Package Quantity=1, Supplier Part Number 1=67AH9250, TOLERANCE=10%, Voltage Rating=25V
C3 C5: "CAP CER 18PF 50V C0G/NP0 0603", Capacitance=18pF, Case Code (Imperial)=0603, Case Code (Metric)=1608, Dielectric=C0G, Dielectric Material=Ceramic, Insulation Resistance=100GR, Manufacturer="KYOCERA AVX", Max Operating Temperature=125°C, Min Operating Temperature=-55°C, Package Quantity=1, Supplier Part Number 1=1349617, Temperature Coefficient=30ppm/°C, TOLERANCE=5%, Voltage=50V
C4 C54 C56 C87 C168 C181 C193 C211: library part CMP-2006-03057-2, "CAP CER 0.1UF 25V X7R 0603", Capacitance=0.10μF, Case/Package=0603, Manufacturer=KEMET, Temperature="-55°C to +125°C", Temperature Characteristic=X7R, Temperature Coefficient=30ppm/°C, Temperature Range High=+125°C, Temperature Range Low=-55°C, TOLERANCE=0.1, Voltage Rating=25V
C6 C102 C103 C113 C114: library part CMP-13271-001434-1, "CAP CER 10UF 25V X7R 1206", Capacitance=10μF, Case Code (Imperial)=1206, Case Code (Metric)=3216, Dielectric=X7R, Manufacturer=SAMSUNG, Max Operating Temperature=125°C, Min Operating Temperature=-55°C, Package Quantity=1, TOLERANCE=10%, Voltage Rating=25V
C7 C18 C23 C26 C37 C42 C44 C55 C69 C75 C86 C89 C90 C115 C128 C142 C155 C157 C158 C162 C164 C165 C166 C178 C187 C194 C195 C231 C247 C269 C270: "CAP CER 2.2UF 50V X5R 0603", Capacitance=2.2μF, Case Code (Imperial)=0603, Case Code (Metric)=1608, Manufacturer=MURATA, Max Operating Temperature=85°C, Min Operating Temperature=-55°C, Ratings=AEC-Q200, TOLERANCE=20%, Voltage Rating=50V
C8 C11 C12 C32 C33 C36 C57 C60 C61 C81 C82 C85 C93 C95 C97 C99 C104 C108 C112 C129 C132 C135 C141 C144 C146 C149 C204 C206 C208 C213 C218 C222 C227 C248 C251 C254 C259 C261 C263 C265: "CAP CER 10UF 25V X7R 1206", Capacitance=10uF, Case Code (Imperial)=1206, Case Code (Metric)=3216, Dielectric=X7R, Manufacturer=SAMSUNG, Max Operating Temperature=125°C, Min Operating Temperature=-55°C, Package Quantity=1, TOLERANCE=10%, Voltage Rating=25V
C9 C35 C58 C84 C94 C145 C205 C262: "CAP CER 2.2UF 25V X7R 1206", Capacitance=2.2μF, Case Code (Imperial)=1206, Case Code (Metric)=3216, Dielectric=X7R, Manufacturer=KYOCERA, Max Operating Temperature=125°C, Min Operating Temperature=-55°C, Package Quantity=2000, Ratings=AEC-Q200, TOLERANCE=10%, Voltage Rating=25V
C38 C45 C48 C53 C172 C175: "CAP CER 1000PF 50V X7R 0603", Case Code (Imperial)=0603, Case Code (Metric)=1608, Dielectric=X7R, Manufacturer=MURATA, Max Operating Temperature=125°C, Min Operating Temperature=-55°C, Package Quantity=4000, Ratings=AEC-Q200, TOLERANCE=10%, Voltage=50V
C39 C41 C50 C52 C64 C67 C96 C101 C106 C107 C134 C137 C140 C148 C150 C174 C177 C207 C217 C220 C221 C253 C255 C258 C264 C266: "CAP CER 0.1UF 50V X7R 0603", Capacitance=100nF, Case Code (Imperial)=0603, Case Code (Metric)=1608, Dielectric=X7R, Manufacturer=TDK, Max Operating Temperature=125°C, Min Operating Temperature=-55°C, Package Quantity=1, Ratings=AEC-Q200, TOLERANCE=10%, Voltage=50V
C40 C46 C47 C51: "CAP CER 10000PF 100V X7R 0603", Case Code (Imperial)=0603, Case Code (Metric)=1608, Dielectric=X7R, Manufacturer=MURATA, Max Operating Temperature=125°C, Min Operating Temperature=-55°C, Package Quantity=4000, TOLERANCE=10%, Voltage=100V
C43 C49 C170 C182 C189 C191: "CAP CER 1UF 35V X7R 0603", Capacitance=1μF, Case Code (Imperial)=0603, Case Code (Metric)=1608, Dielectric=X7R, Manufacturer=TDK, Max Operating Temperature=125°C, Min Operating Temperature=-55°C, Package Quantity=4000, Ratings=AEC-Q200, Supplier Part Number 1=68AH9307, TOLERANCE=10%, Voltage Rating=35V
C100 C105 C109 C111 C130 C133 C138 C139 C216 C219 C223 C226 C249 C252 C256 C257: "CAP CER 330PF 250V C0G/NP0 0603", Capacitance=330pF, Case/Package=0603, Manufacturer=KEMET, Temperature="-55°C to +125°C", Temperature Characteristic=C0G, Temperature Coefficient=30ppm/°C, Temperature Range High=+125°C, Temperature Range Low=-55°C, TOLERANCE=0.05, Voltage Rating=250V
C156 C161 C167 C169 C171 C173 C180 C184 C186 C188 C192 C196 C200 C203 C210 C215: "CAP CER 100PF 50V C0G/NP0 0603", Capacitance=100pF, Case Code (Imperial)=0603, Case Code (Metric)=1608, Dielectric=C0G, Manufacturer=SAMSUNG, Max Operating Temperature=125°C, Min Operating Temperature=-55°C, Package Quantity=1, Supplier Part Number 1=7665130, Temperature Coefficient=300ppm/°C, TOLERANCE=5%, Voltage=50V
C190 C199 C202 C214: "CAP CER 0.27UF 16V X7R 0603", Capacitance=270nF, Case/Package=0603, Dielectric=X7R, Manufacturer=MURATA, TOLERANCE=10%, Voltage=16V
C201 C209: "CAP CER 220PF 100V C0G/NP0 0603", Capacitance=220pF, Case Code (Imperial)=0603, Case Code (Metric)=1608, Dielectric=C0G, Manufacturer=MURATA, Max Operating Temperature=125°C, Min Operating Temperature=-55°C, Package Quantity=1, Ratings=AEC-Q200, Supplier Part Number 1=81-GCM1885C2A221J16D, Temperature Coefficient=30ppm/°C, TOLERANCE=5%, Voltage=100V
D1 D2 D3 D18: "LED GREEN CLEAR CHIP SMD", Case Code (Imperial)=0805, Case Code (Metric)=2012, Color=Green, Forward Current=30mA, Forward Voltage=2.1V, Lens Color=Colorless, Manufacturer=LITE-ON, Max Operating Temperature=85°C, Min Operating Temperature=-55°C, Package Quantity=1, Power Dissipation=100mW, Reverse Voltage=5V, Test Current=10mA
D4 D5 D14 D15 D19 D20 D29 D30: "DIODE SCHOTTKY 30V 200MA SOD123", Case/Package=SOD-123, Manufacturer=MICRO
D6 D7 D12 D13 D16 D21 D22 D27 D28: "LED RED DIFFUSED CHIP SMD", Case/Package=0805, Manufacturer=BROADCOM
D8 D9 D10 D11 D23 D24 D25 D26 D33 D34 D35 D36 D37 D38 D39 D40: library part CMP-004-00052-3, "DIODE GEN PURP 1KV 3A SMC", Case/Package=DO-214AB, Forward Current=3A, Manufacturer="DIODE INC", Peak Inverse Voltage=1kV
D17: "LED YELLOW CLEAR 0805 SMD", Case Code (Imperial)=0805, Case Code (Metric)=2012, Color=Yellow, Forward Current=30mA, Forward Voltage=2V, Lens Color=Colorless, Manufacturer=LITE-ON, Max Operating Temperature=85°C, Max Power Dissipation=75mW, Min Operating Temperature=-55°C, Package Quantity=1, Reverse Voltage=5V, Supplier Part Number 1=6920950, Test Current=20mA
D31 D32 D41 D42: "LED PURPLE CLEAR 1206 SMD", Case/Package=1206, Color=PURPLE, Manufacturer=KINGBRIGHT, Supplier Part Number 1=604-APTR3216-VFX
J1: library part CMP-2000-05417-1, "CONN HEADER VERT 2POS 2.54MM", Case/Package=N/A, Color=White, Current, Rating="5 /  / A", Flammability Rating=UL94V-0, Manufacturer=TE, Temperature, Operating="-55to+105 /  / degC", Voltage, Rating="250 /  / V"
J2 J3 J4 J5 J6 J7 J9 J10: "CONN MMCX JACK STR 50 OHM PCB", Case/Package=N/A, Manufacturer=MOLEX, Max Frequency=6GHz, Package Quantity=500, Supplier Part Number 1=70364031
J8: "CONN HEADER VERT 12POS 2.54MM", Case/Package=N/A, Color=Black, Flammability Rating="UL94 V-0", Manufacturer="WURTH ELEKTRONIK", Manufacturer Print=WURTH, Max Operating Temperature=105°C, Min Operating Temperature=-40°C, Supplier Part Number 1=732-5297-ND, Voltage Rating=250V
J11: "CONN PWR JACK 2X5.5MM SOLDER", Case/Package=N/A, Color=Black, Current Rating=5A, Flammability Rating="UL94 V-0", Insulation Resistance=50MR, Manufacturer="CUI DEVICES", Max Operating Temperature=85°C, Min Operating Temperature=-25°C, Package Quantity=280, Voltage Rating=24V
J12: "CONN D-SUB PLUG 9POS R/A SLDR", Case/Package=N/A, Color=Black, Current Rating=5A, Manufacturer=AMPHENOL, Max Operating Temperature=155°C, Max Supply Voltage (AC)=250V, Min Operating Temperature=-55°C, Supplier Part Number 1=70145033
J13: "PICO-EZMATE HC 1.8 PLUGASSY ETP", Case/Package=N/A, Manufacturer=MOLEX
J14: library part SSW-126-01-G-D_DUAL_CUSTOM, "CONN RCPT 52POS 0.1 GOLD PCB (X2, MODIFIED)", Case/Package=N/A, Manufacturer=SAMTEC, Manufacturer Part Number=SSW-126-01-G-D
L1: library part CMP-006-00021-3, "CMC 100UH 200MA 2LN SMD AEC-Q200", Case/Package=4-SMD, Manufacturer=MURATA, Max Operating Temperature=125°C, Min Operating Temperature=-40°C
MH1 MH4 MH5 MH8: "NYLON HEX NUT M4X07", Case/Package=N/A, Manufacturer=MCMASTER-CARR, Manufacturer Part Number=93800A500
MH2 MH3 MH6 MH7: "SCREW CAP SOCKET HEAD (M4X6)", Case/Package=N/A, Manufacturer=MCMASTER-CARR, Manufacturer Part Number=93070A095
Q1 Q2: "MOSFET N-CH 120V 90A PWRDI5060-8", Case/Package=8-PowerTDFN, Manufacturer="DIODES INC", Supplier Part Number 1=68AH9585
R1 R2 R3 R8 R75 R79 R81 R83 R87 R88 R90 R92: "RES 100K OHM 1% 1/10W 0603", Case Code (Imperial)=0603, Case Code (Metric)=1608, Manufacturer=YAGEO, Max Operating Temperature=155°C, Max Power Dissipation=100mW, Min Operating Temperature=-55°C, Power Rating=0.1W, Resistance=100kΩ, Resistance Tolerance=1%, Resistor Type="Thick Film", Supplier Part Number 1=3697448, Temperature Coefficient=100ppm/°C, Voltage Rating=50V, Working Voltage=75V
R4 R7: "RES 2.7M OHM 5% 1/10W 0603", Case Code (Imperial)=0603, Case Code (Metric)=1608, Manufacturer=YAGEO, Max Operating Temperature=155°C, Max Power Dissipation=100mW, Min Operating Temperature=-55°C, Package Quantity=1, Power Rating=0.1W, Resistance=2.7MΩ, Resistor Type="Thick Film", Temperature Coefficient=100ppm/°C, TOLERANCE=5%, Voltage Rating=75V, Voltage Rating (DC)=50V
R5 R6 R21 R25 R43 R49 R105 R111 R146 R150: "RES SMD 0 OHM JUMPER 3/4W 1210", Case Code (Imperial)=1210, Case Code (Metric)=3225, Manufacturer="VISHAY DALE", Max Operating Temperature=155°C, Max Power Dissipation=750mW, Min Operating Temperature=-55°C, Package Quantity=10, Resistance=0Ω, Supplier Part Number 1=71-CRCW12100000Z0EAH
R9 R218 R222 R227 R230 R234 R241 R242 R243 R258 R259 R272 R273 R289 R290: "RES SMD 20K OHM 1% 1/10W 0603", Case Code (Imperial)=0603, Case Code (Metric)=1608, Manufacturer="VISHAY DALE", Max Operating Temperature=155°C, Max Power Dissipation=100mW, Min Operating Temperature=-55°C, Package Quantity=5000, Power Rating=0.1W, Resistance=20kΩ, Resistance Tolerance=1%, Resistor Type="Thick Film", Temperature Coefficient=100ppm/°C, Voltage Rating=75V
R10: "RES SMD 2K OHM 0.5% 1/10W 0603", Case Code (Imperial)=0603, Case Code (Metric)=1608, Manufacturer=YAGEO, Max Operating Temperature=125°C, Max Power Dissipation=100mW, Min Operating Temperature=-55°C, Package Quantity=5000, Power Rating=0.1W, Resistance=2kΩ, Resistor Type="Thin Film", Supplier Part Number 1=6165116, Temperature Coefficient=50ppm/°C, TOLERANCE=0.5%, Voltage Rating=75V, Voltage Rating (DC)=50V
R11 R12 R14 R15 R62 R63 R68 R73 R162 R163 R191 R192 R194 R195 R196 R197 R198 R199 R200 R201 R203 R204 R235 R236 R249 R250 R254 R257 R261 R268 R283 R291 R292 R305 R332 R333 R337 R339 R340 R342 R343 R345 R346 R349 R353 R354 R376 R377: "RES SMD 120 OHM 5% 1/10W 0603", Case Code (Imperial)=0603, Case Code (Metric)=1608, Manufacturer=YAGEO, Max Operating Temperature=155°C, Max Power Dissipation=0.1W, Min Operating Temperature=-55°C, Package Quantity=1, Power Rating=100mW, Resistance Tolerance=5%, Resistor Type="Thick Film", Supplier Part Number 1=2424206, Temperature Coefficient=100ppm/°C, Voltage Rating=50V
R13: "RES 0.01 OHM 1% 2W 2512", Case Code (Imperial)=2512, Case Code (Metric)=6432, Manufacturer=YAGEO, Max Operating Temperature=170°C, Max Power Dissipation=2W, Min Operating Temperature=-55°C, Resistance=10mΩ, Resistor Type="Metal Film", Supplier Part Number 1=1995902P, Temperature Coefficient=50ppm/°C, TOLERANCE=1%
R16 R17 R18 R23 R26 R27 R40 R42 R45 R46 R52 R53 R55 R57 R94 R96 R99 R109 R113 R116 R144 R145 R148 R153 R154 R155: "RES SMD 120 OHM 5% 1/10W 0603", Case Code (Imperial)=0603, Case Code (Metric)=1608, Manufacturer=YAGEO, Max Operating Temperature=155°C, Min Operating Temperature=-55°C, Package Quantity=1, Power Rating=100mW, Resistance Tolerance=5%, Resistor Type="Thick Film", Supplier Part Number 1=2424206, Temperature Coefficient=100ppm/°C, Voltage Rating=50V
R19 R20 R50 R51 R67 R70 R71 R72 R76 R77 R78 R82 R97 R103 R104 R114 R115 R117 R118 R119 R120 R123 R124 R127 R128 R131 R132 R133 R134 R135 R136 R151 R152 R160 R161 R173 R185 R211 R228 R303 R323 R361 R373: "RES SMD 0 OHM JUMPER 1/10W 0603", Case Code (Imperial)=0603, Case Code (Metric)=1608, Manufacturer="VISHAY DALE", Max Operating Temperature=155°C, Max Power Dissipation=100mW, Min Operating Temperature=-55°C, Package Quantity=10000, Ratings=AEC-Q200, Resistance=0Ω, Resistor Type="Thick Film", Supplier Part Number 1=48P7902, Temperature Coefficient=100ppm/°C, TOLERANCE=1%, Voltage Rating=75V
R22 R24 R44 R48 R106 R110 R147 R149: library part CMP-2005-02198-1, "RES 0.91 OHM 1% 1W 1210", Case/Package=1210, Manufacturer="VISHAY DALE"
R28 R29 R38 R39 R121 R122 R142 R143: "RES SMD 220 OHM 1% 1/10W 0603", Case/Package=0603, Manufacturer=YAGEO, Power Rating=0.1W, Resistance=220Ω, Temperature="-55°C to +155°C", Temperature Coefficient="50 ppm/°C", Temperature Range High=+155°C, Temperature Range Low=-55°C, TOLERANCE=0.01, Voltage Rating=75V
R30 R31 R32 R33 R34 R35 R36 R37 R125 R126 R129 R130 R138 R139 R140 R141: "RES 2.2K OHM 1% 1/10W 0603", Case/Package=0603, Manufacturer=YAGEO, POWER=0.1W
R41 R47 R137 R178 R179 R216 R217 R269 R313 R314 R315 R316 R319 R326 R330 R331 R334 R335 R338 R341 R344 R347 R348 R351 R352 R366 R367: "RES SMD 10K OHM 1% 1/10W 0603", Case Code (Imperial)=0603, Case Code (Metric)=1608, Manufacturer=PANASONIC, Manufacturer Part Number=ERJ-3EKF1002V, Max Operating Temperature=155°C, Max Power Dissipation=0.1W, Min Operating Temperature=-55°C, Package Quantity=1, Power Rating=100mW, Resistance=10kΩ, Resistance Tolerance=1%, Resistor Type="Thick Film", Supplier Part Number 1=1051156, Temperature Coefficient=100ppm/°C, Voltage Rating=75V
R58 R59 R60 R61 R167 R168 R169 R170 R229 R233 R288: "RES 330 OHM 1% 1/10W 0603", Case Code (Imperial)=0603, Case Code (Metric)=1608, Manufacturer=YAGEO, Max Operating Temperature=155°C, Min Operating Temperature=-55°C, Power Rating=0.1W, Resistance=330Ω, Resistor Type="Thick Film", Supplier Part Number 1=4067719, Temperature Coefficient=100ppm/°C, TOLERANCE=1%, Voltage Rating=50V
R64 R65 R66 R84 R85 R86 R251 R252 R253 R274 R275 R276: "RES SMD 1M OHM 0.1% 1/3W 1206", Case/Package=1206, Manufacturer=STACKPOLE, Max Operating Temperature=155°C, Min Operating Temperature=-55°C, Package Height=0.55mm, Package Length=3.05mm, Package Shape=Rectangular, Package Width=1.55mm, POWER=0.33W, Rated Temperature=70°C, Resistor Type="FIXED RESISTOR", Supplier Part Number=RNCF1206BKE1M00CT-ND, Temperature Coefficient (ppm/Cel)=25, TOLERANCE=0.1%, Working Voltage=200V
R69 R80 R95 R98 R102 R108 R164 R165 R188 R189 R190 R193 R202 R205 R206 R207 R231 R232 R255 R270 R286 R295 R297 R309 R327 R328 R329 R336 R350 R355 R356 R357 R374 R375: "RES SMD 10K OHM 1% 1/10W 0603", Case Code (Imperial)=0603, Case Code (Metric)=1608, Manufacturer=PANASONIC, Manufacturer Part Number=ERJ-3EKF1002V, Max Operating Temperature=155°C, Max Power Dissipation=0.1W, Min Operating Temperature=-55°C, Package Quantity=1, Power Rating=100mW, Resistance Tolerance=1%, Resistor Type="Thick Film", Supplier Part Number 1=1051156, Temperature Coefficient=100ppm/°C, Voltage Rating=75V
R74 R282 R285 R299 R304: "RES SMD 49.9 OHM 1% 1/10W 0603", Case Code (Imperial)=0603, Case Code (Metric)=1608, Manufacturer=PANASONIC, Max Operating Temperature=155°C, Max Power Dissipation=100mW, Min Operating Temperature=-55°C, Package Quantity=5000, Power Rating=0.1W, Resistance=49.9Ω, Resistance Tolerance=1%, Resistor Type="Thick Film", Supplier Part Number 1=12AC1058, Temperature Coefficient=100ppm/°C, Voltage Rating=75V, Voltage Rating (DC)=50V, Working Voltage=6V
R89 R91: "RES 100K OHM 1% 1/10W 0603", Case Code (Imperial)=0603, Case Code (Metric)=1608, Manufacturer=YAGEO, Max Operating Temperature=155°C, Max Power Dissipation=100mW, Min Operating Temperature=-55°C, Resistance=100kΩ, Resistance Tolerance=1%, Resistor Type="Thick Film", Supplier Part Number 1=3697448, Temperature Coefficient=100ppm/°C, Voltage Rating=50V, Working Voltage=75V
R93: library part CMP-06022-000547-2, "THERMISTOR NTC 10KOHM 3380K 0603", Case Code (Imperial)=0603, Case Code (Metric)=1608, Manufacturer=MURATA, Max Operating Temperature=150°C, Min Operating Temperature=-40°C
R100 R107: "RES 10 OHM 5% 1/10W 0603", Case/Package=0603, Manufacturer=YAGEO, POWER=0.1W
R101 R112 R298 R308: "RES SMD 16.5KOHM 0.5% 1/10W 0603", Case/Package=0603, Manufacturer=YAGEO, Power Rating=0.1W, Resistance=16.5kΩ, Temperature="-55°C to +155°C", Temperature Coefficient="25 ppm/°C", Temperature Range High=+155°C, Temperature Range Low=-55°C, TOLERANCE=0.005, Voltage Rating=75V
R156 R157 R158 R159 R382 R383 R384 R385: "RES 249 OHM 1% 1/4W 1206", Case Code (Imperial)=1206, Case Code (Metric)=3216, Manufacturer=YAGEO, Max Operating Temperature=155°C, Max Power Dissipation=250mW, Min Operating Temperature=-55°C, Power Rating=0.25W, Resistance=249Ω, Resistor Type="Thick Film", Supplier Part Number 1=1142064, Temperature Coefficient=100ppm/°C, TOLERANCE=1%, Voltage Rating=200V
R166 R180 R210 R226 R296 R317 R360 R372: "RES 330 OHM 5% 1/2W 1210", Case/Package=1210, Manufacturer=YAGEO, POWER=0.5W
